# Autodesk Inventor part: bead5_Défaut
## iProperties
Shininess: 64.0
Length Units: 11269
Angle Units: 11279
Time Units: 11290
Mass Units: 11283
Length Display Precision: 3
Angle Display Precision: 2
Compacted: True
Part Number: bead5_Défaut
Document SubType Name: Modeling
Created: 2006-11
Material: Par défaut
Designer: profs_sti
Density: 0.0
Volumn: 0.0
Area: 0.0
PropertySet Name: Model Information
Control State: 0
Master: False
Checked Out: False
Author: profs_sti
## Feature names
1. Base1
